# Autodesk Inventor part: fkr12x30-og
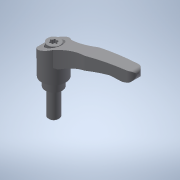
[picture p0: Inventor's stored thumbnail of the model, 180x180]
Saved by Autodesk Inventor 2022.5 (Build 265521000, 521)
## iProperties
Created: 2017-09
Part Number: fkr12x30-og
Material: 一般
Document SubType Name: Modeling
Designer: imaocorp
Density: 1 g/cm^3
Appearance: 既定
Author: imaocorp
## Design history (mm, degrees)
node "fkr12x30-og.x_t1"
node "fkr12x30-og"
node "Base1"
